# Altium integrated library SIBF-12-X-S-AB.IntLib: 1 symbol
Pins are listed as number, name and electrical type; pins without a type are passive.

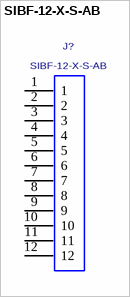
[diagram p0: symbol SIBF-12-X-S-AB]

## SIBF-12-X-S-AB
designator J?
.050" SIBF ASSEMBLY.; MANUFACTURER: SAMTEC
footprint SIBF-12-X-S-AB
pins: 1, 2, 3, 4, 5, 6, 7, 8, 9, 10, 11, 12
